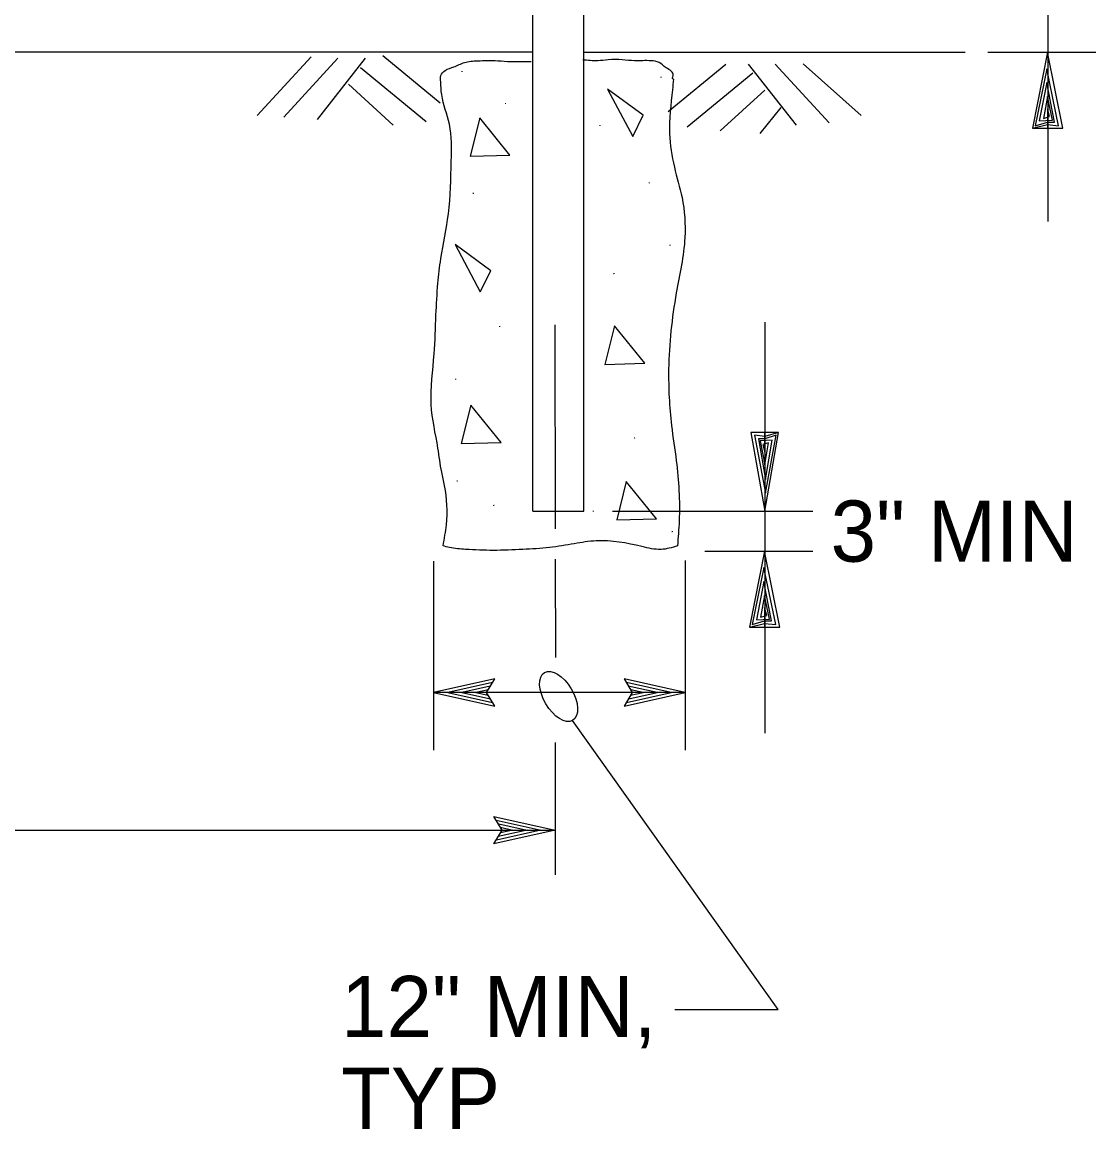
# Model space of a CAD drawing. Extents: x -123486 to -116575, y -107066 to -101122.
# Drawn here: x -117999.6 to -117894.2, y -102116.1 to -102007.5 of the extents above; entities that cross this region are included whole.
import ezdxf

# ---------------------------------------------------------------- set-up
doc = ezdxf.new("R2010")
doc.units = 0
for name, color, linetype in [('G-MARK', 7, 'Continuous'), ('G-TEXT', 7, 'Continuous'), ('Misc CnstDet(22)', 7, 'Continuous'), ('Nongeo Data(60)', 7, 'Continuous'), ('S-FNDN-PILE', 7, 'Continuous')]:
    doc.layers.add(name, color=color, linetype=linetype)

# ---------------------------------------------------------------- blocks, each defined once
blk = doc.blocks.new('ARROW')
at = {"layer": 'S-FNDN-PILE'}
blk.add_lwpolyline([(-0.002083, 0.000367), (-0.002083, -0.000367), (0, 0), (-0.002083, 0.000367), (-0.001983, 0), (-0.002017, -0.000267), (-0.00045, 0.000017), (-0.002017, 0.0003), (-0.001917, 0), (-0.001917, -0.000167), (-0.000833, 0.000017), (-0.001883, 0.0002), (-0.001867, -0.000117), (-0.001217, 0), (-0.001817, 0.0001), (-0.001767, -0.00005), (-0.00155, 0), (-0.002083, 0)], dxfattribs=at)

msp = doc.modelspace()

# ---------------------------------------------------------------- linework, layer by layer
at = {"layer": 'G-MARK'}
for p, q in [((-117898.96, -101975.97), (-117898.96, -102027.09)), ((-117904.83, -102010.5), (-117894.23, -102010.5)), ((-117926.72, -102036.97), (-117926.72, -102077.29)), ((-117941.67, -102055.5), (-117921.99, -102055.5)), ((-117932.59, -102059.44), (-117921.99, -102059.44)), ((-117959.23, -102060.42), (-117959.23, -102078.95)), ((-117934.52, -102060.37), (-117934.52, -102078.95)), ((-117934.52, -102073.29), (-117959.21, -102073.31)), ((-117925.4, -102104.4), (-117945.58, -102076.04)), ((-118359.71, -102086.81), (-117947.29, -102086.81)), ((-117935.54, -102104.4), (-117925.4, -102104.4))]:
    msp.add_line(p, q, dxfattribs=at)
for points in [[(-117947.31, -102037.24), (-117947.29, -102057.24)], [(-117947.28, -102060.24), (-117947.27, -102069.88)], [(-117947.28, -102078.22), (-117947.29, -102091.18)]]:
    msp.add_lwpolyline(points, dxfattribs=at)
msp.add_ellipse((-117946.95, -102073.69), major_axis=(-1.38, 2.35), ratio=0.531478, dxfattribs=at)
at = {"layer": 'G-TEXT'}
for p, q in [((-117953.21, -102071.97), (-117959.21, -102073.31)), ((-117954.01, -102073.31), (-117953.21, -102071.97)), ((-117953.21, -102071.97), (-117953.21, -102071.97)), ((-117934.52, -102073.29), (-117940.52, -102071.96)), ((-117940.52, -102071.96), (-117940.52, -102071.96)), ((-117940.52, -102071.96), (-117939.72, -102073.29)), ((-117959.21, -102073.31), (-117959.21, -102073.31)), ((-117959.21, -102073.31), (-117953.21, -102074.64)), ((-117953.43, -102072.32), (-117957.83, -102073.31)), ((-117957.82, -102073.32), (-117953.44, -102074.28)), ((-117953.66, -102072.68), (-117956.45, -102073.31)), ((-117956.45, -102073.31), (-117953.62, -102073.93)), ((-117953.84, -102073.03), (-117955.07, -102073.31)), ((-117955.07, -102073.31), (-117953.86, -102073.57)), ((-117953.21, -102074.64), (-117954.01, -102073.31)), ((-117939.72, -102073.29), (-117940.52, -102074.63)), ((-117940.52, -102074.63), (-117934.52, -102073.29)), ((-117940.3, -102074.28), (-117935.9, -102073.29)), ((-117935.91, -102073.29), (-117940.28, -102072.32)), ((-117937.28, -102073.29), (-117940.11, -102072.67)), ((-117940.07, -102073.92), (-117937.28, -102073.29)), ((-117939.89, -102073.57), (-117938.66, -102073.3)), ((-117938.66, -102073.3), (-117939.87, -102073.03)), ((-117934.52, -102073.29), (-117934.52, -102073.29)), ((-117953.21, -102074.64), (-117953.21, -102074.64)), ((-117940.52, -102074.63), (-117940.52, -102074.63)), ((-117952.49, -102086.81), (-117953.29, -102085.47)), ((-117953.29, -102085.47), (-117953.29, -102085.47)), ((-117953.29, -102085.47), (-117947.29, -102086.81)), ((-117953.07, -102085.82), (-117948.67, -102086.81)), ((-117952.83, -102086.18), (-117950.05, -102086.8)), ((-117947.29, -102086.81), (-117953.29, -102088.14)), ((-117953.29, -102088.14), (-117952.49, -102086.81)), ((-117948.68, -102086.81), (-117953.05, -102087.78)), ((-117950.05, -102086.8), (-117952.87, -102087.43)), ((-117952.66, -102086.53), (-117951.43, -102086.8)), ((-117951.43, -102086.8), (-117952.64, -102087.07)), ((-117947.29, -102086.81), (-117947.29, -102086.81)), ((-117953.29, -102088.14), (-117953.29, -102088.14))]:
    msp.add_line(p, q, dxfattribs=at)
msp.add_lwpolyline([(-117925.36, -102047.81), (-117928.09, -102047.81), (-117926.72, -102055.5), (-117925.36, -102047.81), (-117926.72, -102048.18), (-117927.72, -102048.06), (-117926.66, -102053.76), (-117925.61, -102048.06), (-117926.72, -102048.43), (-117927.34, -102048.43), (-117926.66, -102052.4), (-117925.98, -102048.55), (-117927.16, -102048.62), (-117926.72, -102050.97), (-117926.35, -102048.8), (-117926.91, -102048.99), (-117926.72, -102049.73), (-117926.72, -102047.81)], dxfattribs=at)
at = {"layer": 'Nongeo Data(60)'}
for p, q in [((-117949.48, -102055.5), (-117949.48, -101996.14)), ((-117944.48, -102055.5), (-117944.48, -101996.14)), ((-117949.48, -102010.5), (-118153.48, -102010.5)), ((-117971.23, -102010.94), (-117976.52, -102016.7)), ((-117968.6, -102011.09), (-117973.9, -102016.85)), ((-117965.94, -102011.09), (-117970.64, -102017.08)), ((-117964.21, -102010.81), (-117958.57, -102015.45)), ((-117944.48, -102010.5), (-117907.06, -102010.5)), ((-117966.4, -102011.99), (-117959.96, -102017.3)), ((-117930.55, -102011.69), (-117936.19, -102016.33)), ((-117928.35, -102011.66), (-117923.65, -102017.64)), ((-117925.69, -102011.66), (-117920.39, -102017.42)), ((-117922.95, -102011.62), (-117917.25, -102016.7)), ((-117927.89, -102012.56), (-117934.33, -102017.86)), ((-117967.58, -102013.64), (-117963.18, -102017.65)), ((-117926.71, -102014.21), (-117931.11, -102018.22)), ((-117925.15, -102015.93), (-117927.21, -102018.46)), ((-117949.48, -102055.5), (-117944.48, -102055.5)), ((-117949.48, -102055.5), (-117944.48, -102055.5)), ((-117949.48, -102055.5), (-117944.48, -102055.5))]:
    msp.add_line(p, q, dxfattribs=at)
for points in [[(-117942.15, -102014.11), (-117939.68, -102018.76), (-117938.65, -102016.68)], [(-117955.63, -102020.69), (-117951.73, -102020.58), (-117954.69, -102016.92)], [(-117957.11, -102029.36), (-117954.63, -102034.01), (-117953.61, -102031.93)], [(-117942.4, -102041.12), (-117938.5, -102041.01), (-117941.46, -102037.35)], [(-117956.5, -102048.88), (-117952.6, -102048.78), (-117955.55, -102045.12)], [(-117941.25, -102056.37), (-117937.35, -102056.26), (-117940.31, -102052.6)]]:
    msp.add_lwpolyline(points, close=True, dxfattribs=at)
for points in [[(-117958.51, -102013.4), (-117958.51, -102012.79), (-117958.08, -102012.27), (-117957.22, -102011.93), (-117956.19, -102011.5), (-117954.9, -102011.33), (-117952.92, -102011.33), (-117951.63, -102011.41), (-117950.25, -102011.41), (-117949.65, -102011.41)], [(-117935.67, -102013.14), (-117935.72, -102013.13), (-117935.72, -102012.79), (-117935.89, -102012.36), (-117936.41, -102012.01), (-117937.09, -102011.5), (-117937.87, -102011.33), (-117939.5, -102011.33), (-117940.71, -102011.24), (-117942.08, -102011.24), (-117943.11, -102011.33), (-117944.58, -102011.24)], [(-117958.29, -102058.92), (-117957.95, -102056.84), (-117958.14, -102053), (-117958.42, -102051.69), (-117958.79, -102049.35), (-117959.45, -102045.05), (-117959.16, -102040.09), (-117958.98, -102036.26), (-117958.79, -102033.17), (-117958.51, -102030.74), (-117957.76, -102026.34), (-117957.48, -102021.19), (-117957.67, -102017.55), (-117958.42, -102014.65), (-117958.51, -102013.4)], [(-117935.67, -102013.14), (-117935.78, -102014.18), (-117936.06, -102018.48), (-117935.59, -102021.76), (-117934.84, -102024.75), (-117934.56, -102028.68), (-117935.4, -102034.1), (-117936.15, -102041.59), (-117935.87, -102047.11), (-117935.4, -102050.57), (-117935.12, -102056.46), (-117935.29, -102058.92)], [(-117935.29, -102058.92), (-117936.9, -102059.27), (-117938.77, -102058.99), (-117943.26, -102058.43), (-117945.41, -102058.71), (-117947.84, -102059.08), (-117950.46, -102059.27), (-117953.36, -102059.36), (-117956.08, -102059.27), (-117957.67, -102059.08), (-117958.29, -102058.92)]]:
    msp.add_spline(points, degree=3, dxfattribs=at)

# ---------------------------------------------------------------- block references
at = {"layer": 'G-TEXT', "xscale": 3571.703056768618, "yscale": 4058.0876675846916, "rotation": 90}
for p in [(-117898.97, -102010.5), (-117926.73, -102059.44)]:
    msp.add_blockref('ARROW', p, dxfattribs=at)

# ---------------------------------------------------------------- texts
at = {"layer": 'Misc CnstDet(22)'}
msp.add_text('3" MIN', height=6, rotation=360, dxfattribs=at).set_placement((-117920.26, -102060.47))
for s, p in [('12" MIN,', (-117968.3, -102107.11)), ('TYP', (-117968.3, -102116.11))]:
    msp.add_text(s, height=6, dxfattribs=at).set_placement(p)
at = {"layer": 'Nongeo Data(60)'}
for p in [(-117956.37, -102012.52), (-117936.84, -102013.09), (-117952.09, -102015.68), (-117942.83, -102017.82), (-117937.99, -102023.44), (-117955.25, -102024.48), (-117935.95, -102029.56), (-117941.44, -102032.36), (-117952.66, -102037.54), (-117956.98, -102042.72), (-117939.43, -102048.48), (-117956.83, -102052.7), (-117953.24, -102055.09), (-117943.46, -102055.67), (-117935.73, -102057.67)]:
    msp.add_text('.', height=0.8, rotation=93.0685, dxfattribs=at).set_placement(p)

doc.saveas('drawing.dxf')
